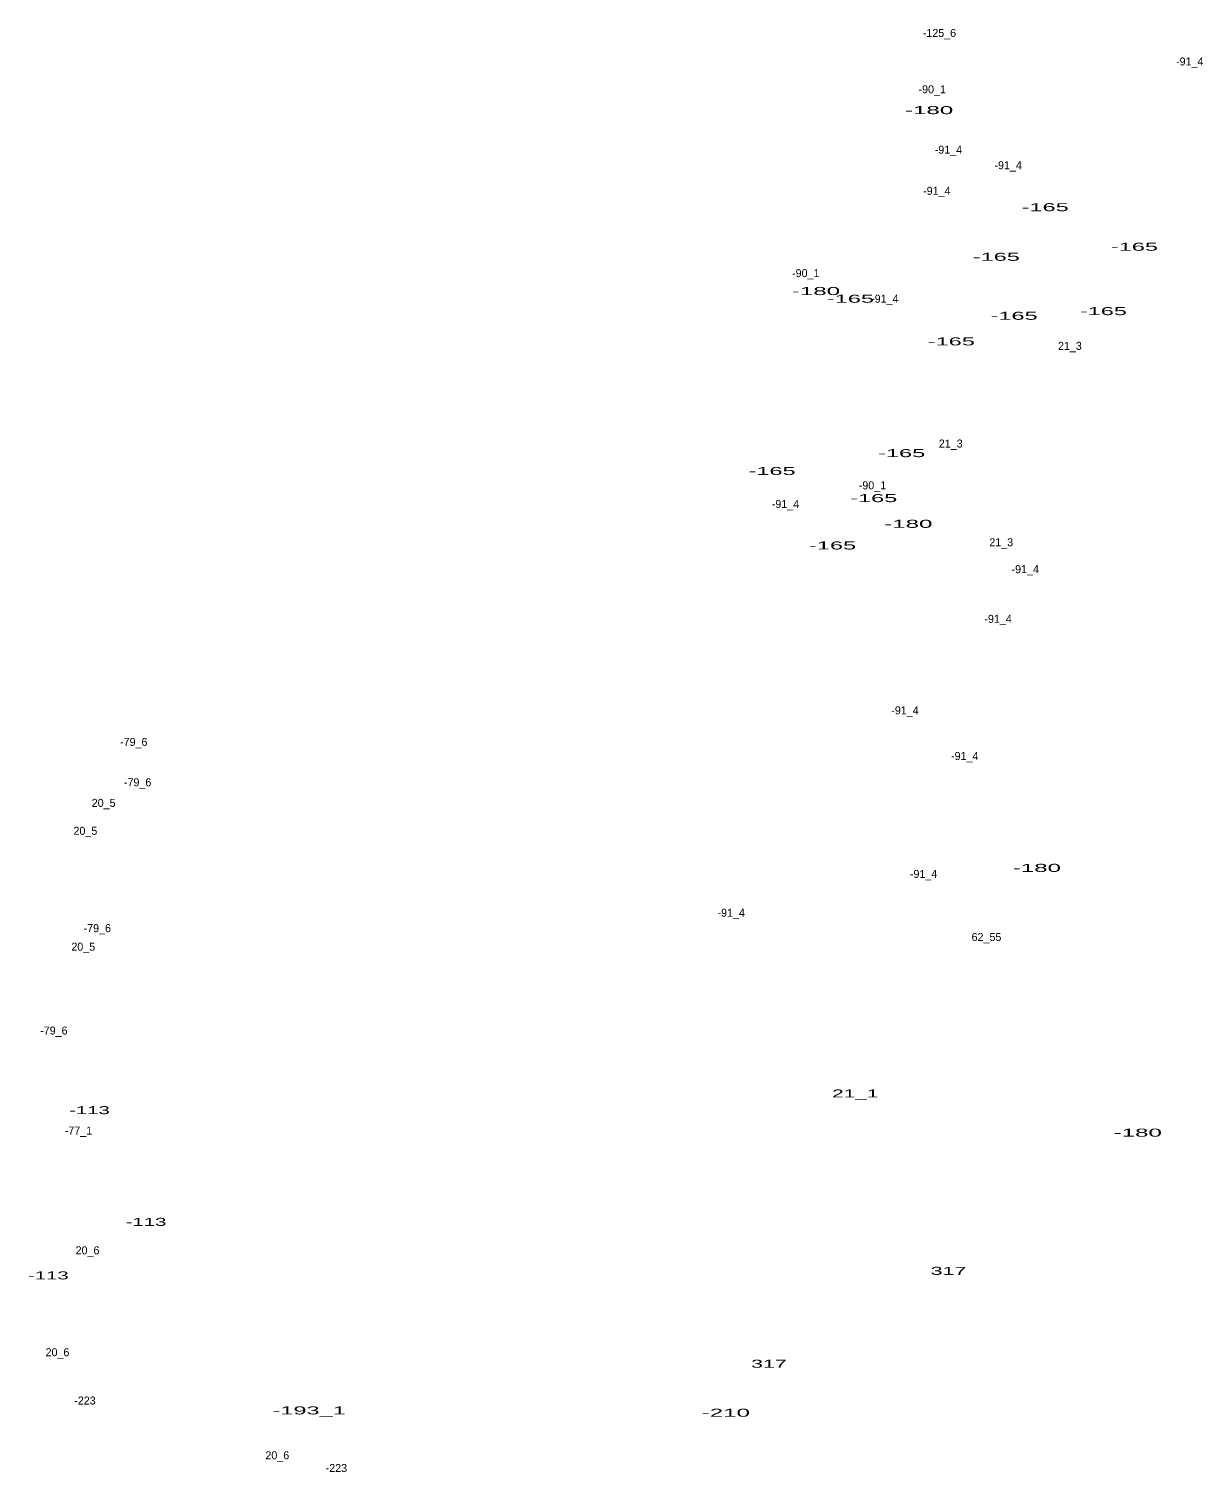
# Model space of a CAD drawing. Extents: x -661742 to -657295, y -1002932 to -996888.
# Drawn here: x -659227 to -658640, y -998356 to -997635 of the extents above; entities that cross this region are included whole.
import ezdxf
from ezdxf.enums import TextEntityAlignment as Align

# ---------------------------------------------------------------- set-up
doc = ezdxf.new("R2010")
doc.units = 0
doc.header["$LTSCALE"] = 1.6
doc.layers.add('24', color=7, linetype='Continuous')

msp = doc.modelspace()

# ---------------------------------------------------------------- texts
at = {"layer": '24'}
for s, p in [('-125_6', (-658772.242, -997638.7)), ('-91_4', (-658647.166, -997652.93)), ('-90_1', (-658775.846, -997666.84)), ('-91_4', (-658767.746, -997697.04)), ('-91_4', (-658737.896, -997704.8)), ('-91_4', (-658773.566, -997717.6)), ('-90_1', (-658839.046, -997758.77)), ('-91_4', (-658799.546, -997771.52)), ('21_3', (-658707.059, -997795.11)), ('21_3', (-658766.589, -997843.94)), ('-90_1', (-658805.706, -997864.83)), ('-91_4', (-658849.176, -997874.16)), ('21_3', (-658741.379, -997893.3)), ('-91_4', (-658729.366, -997906.74)), ('-91_4', (-658742.936, -997931.57)), ('-91_4', (-658789.466, -997977.34)), ('-79_6', (-659174.838, -997993.12)), ('-91_4', (-658759.606, -998000.15)), ('-79_6', (-659172.898, -998013.29)), ('20_5', (-659189.879, -998023.59)), ('20_5', (-659198.999, -998037.54)), ('-91_4', (-658780.156, -998059.11)), ('-91_4', (-658876.316, -998078.5)), ('-79_6', (-659193.058, -998086.21)), ('62_55', (-658748.74, -998090.63)), ('20_5', (-659200.069, -998095.48)), ('-79_6', (-659214.768, -998137.41)), ('-77_1', (-659202.477, -998187.39)), ('20_6', (-659197.934, -998247.26)), ('20_6', (-659212.954, -998298.23)), ('-223', (-659199.215, -998322.36)), ('20_6', (-659103.104, -998349.74)), ('-223', (-659073.585, -998356.1))]:
    msp.add_text(s, height=4, dxfattribs=at).set_placement(p, align=Align.CENTER)
for s, width, p in [('-180', 2.25, (-658777.407, -997677.27)), ('-165', 2.2, (-658719.395, -997725.78)), ('-165', 2.2, (-658674.805, -997745.56)), ('-165', 2.2, (-658743.815, -997750.6)), ('-180', 2.25, (-658833.947, -997767.72)), ('-165', 2.2, (-658816.715, -997771.55)), ('-165', 2.2, (-658734.905, -997780.08)), ('-165', 2.2, (-658690.315, -997777.75)), ('-165', 2.2, (-658766.305, -997792.88)), ('-165', 2.2, (-658791.125, -997848.74)), ('-165', 2.2, (-658855.875, -997857.66)), ('-165', 2.2, (-658805.085, -997871.23)), ('-180', 2.25, (-658787.797, -997884.08)), ('-165', 2.2, (-658825.635, -997894.89)), ('-180', 2.25, (-658723.557, -998056.07)), ('21_1', 1.95, (-658814.315, -998168.86)), ('-113', 1.9, (-659196.977, -998177.19)), ('-180', 2.25, (-658673.147, -998188.45)), ('-113', 1.9, (-659168.677, -998233.05)), ('317', 2, (-658767.713, -998257.53)), ('-113', 1.9, (-659217.527, -998259.81)), ('317', 2, (-658857.443, -998303.96)), ('-193_1', 2.2, (-659087.213, -998327.3)), ('-210', 2.25, (-658878.967, -998328.46))]:
    msp.add_text(s, height=4, dxfattribs=dict(at, width=width)).set_placement(p, align=Align.CENTER)

doc.saveas('drawing.dxf')
